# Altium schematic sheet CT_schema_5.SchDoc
size 251 x 159 mm
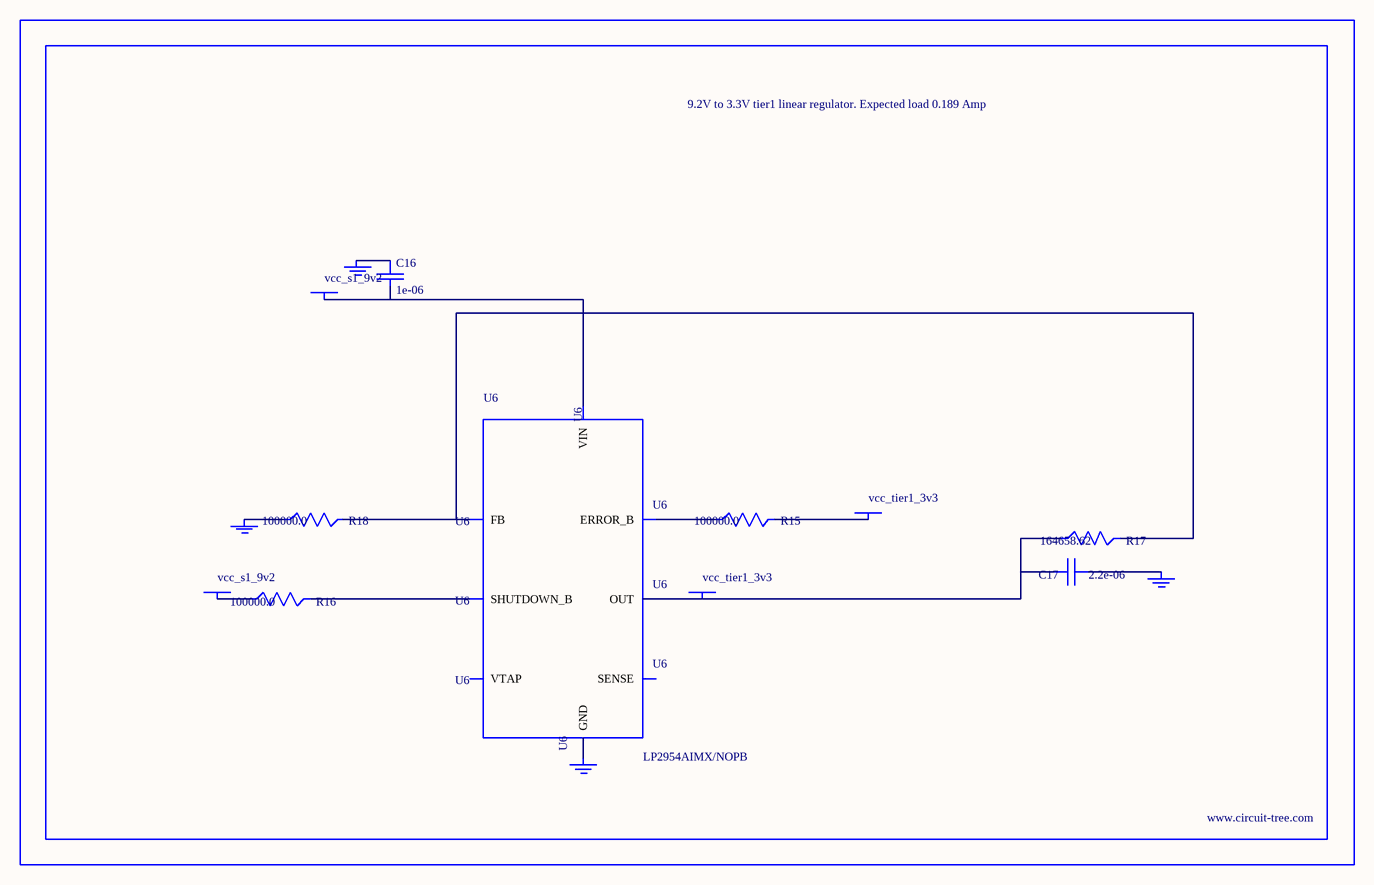
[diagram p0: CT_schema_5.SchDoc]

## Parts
BORDER4  (no value)
C16  1e-06  [EXV-9B]
C17  2.2e-06  [EXV-9B]
GND_INSTANCE_4_0  (no value)
GND_INSTANCE_4_1  (no value)
GND_INSTANCE_4_2  (no value)
GND_INSTANCE_4_3  (no value)
POWER_INSTANCE_4_0  vcc_s1_9v2
POWER_INSTANCE_4_1  vcc_tier1_3v3
POWER_INSTANCE_4_2  vcc_s1_9v2
POWER_INSTANCE_4_3  vcc_tier1_3v3
R15  100000.0  [R0603]
R16  100000.0  [R0603]
R17  164658.62  [R0603]
R18  100000.0  [R0603]
U6  LP2954AIMX/NOPB  [LP2954]

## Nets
NetC16_1: C16.1 GND_INSTANCE_4_2.0(GND)
NetC16_2: C16.2 POWER_INSTANCE_4_2.0(PWR) U6.8(VIN)
NetC17_1: C17.1 GND_INSTANCE_4_0.0(GND)
NetC17_2: C17.2 POWER_INSTANCE_4_3.0(PWR) R17.1 U6.1(OUT)
NetGND_INSTANCE_4_1_0: GND_INSTANCE_4_1.0(GND) R18.1
NetGND_INSTANCE_4_3_0: GND_INSTANCE_4_3.0(GND) U6.4(GND)
NetPOWER_INSTANCE_4_0_0: POWER_INSTANCE_4_0.0(PWR) R16.1
NetPOWER_INSTANCE_4_1_0: POWER_INSTANCE_4_1.0(PWR) R15.2
NetR15_1: R15.1 U6.5(ERROR_B)
NetR16_2: R16.2 U6.3(SHUTDOWN_B)
NetR17_2: R17.2 R18.2 U6.7(FB)

Not connected (* = marked no-connect by the designer): U6 2(SENSE) 6(VTAP)

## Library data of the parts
BORDER4 = BORDER_PAGE4
C16 = EDK105M050A9BAA
C17 = EDK225M050A9BAA
GND_INSTANCE_4_0-GND_INSTANCE_4_3 = GND
POWER_INSTANCE_4_0-POWER_INSTANCE_4_3 = PWR
R15 R16 R18 = RC0603JR-07100KL
R17 = R17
